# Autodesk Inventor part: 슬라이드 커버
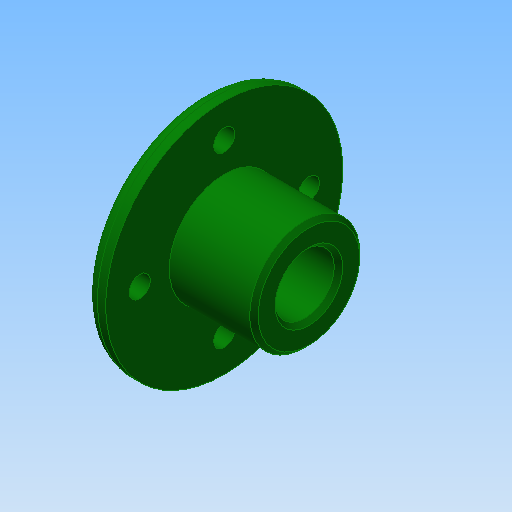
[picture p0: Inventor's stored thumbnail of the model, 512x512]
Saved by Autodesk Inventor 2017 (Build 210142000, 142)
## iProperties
Created: 2015-12
Part Number: 슬라이드 커버
Document SubType Name: Modeling
Designer: mdu
Density: 2.71 g/cm^3
Material: 알루미늄 6061
Appearance: 진녹색
Mass: 49.5251 g
Surface Area: 80.5945 cm^2
Volume: 18.2749 cm^3
Author: mdu
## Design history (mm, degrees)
sketch "스케치1"
  geometry: L1 (-12.5, 0)-(12.5, 0); L2 (-12.5, 0)-(-12.5, 28); L3 (-12.5, 28)-(-7.5, 28); L4 (-7.5, 28)-(-7.5, 13); L5 (-7.5, 13)-(12.5, 13); L6 (12.5, 13)-(12.5, 0); 2 further points
  constraints: 12 end point, 3 perpendicular, 1 coincident, 1 horizontal, 1 midpoint, 1 parallel
  dimensions: "d1" = 56 diameter of L3 L1; "d2" = 26 diameter of L5 L1; "d5" = 5 distance of L2.end L3.end; "d32" = 20 distance of L4.end L5.end
revolve "회전1" sketch "스케치1" stored, may be unused: angle "d6" = 90 deg
sketch "스케치2" dims "d33" = 40
  geometry: 3 further points
  constraints: 2 vertical alignment, 1 coincident, 2 other
hole "구멍1" sketch "스케치2" at (0, 20) diameter "d8" = 5; stored, may be unused: countersink angle "d12" = 90 deg, drill point angle "d14" = 118 deg; dims "d9" = 6, "d10" = 8, "d11" = 4.4, "d13" = 8
hole "구멍2" diameter "d20" = 14; stored, may be unused: countersink angle "d24" = 90 deg, drill point angle "d26" = 0 deg; dims "d18" = 10, "d19" = 10, "d21" = 6, "d22" = 8, "d23" = 4.4, "d25" = 8
fillet "모깎기1" dims "d27" = 3
chamfer "모따기1" distance "d29" = 1; stored, may be unused: second distance "d30" = 2, angle "d31" = 45 deg
node "솔리드1"
pattern_circular "원형 패턴1" dims angle "d16" = 360 deg
